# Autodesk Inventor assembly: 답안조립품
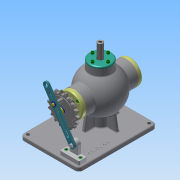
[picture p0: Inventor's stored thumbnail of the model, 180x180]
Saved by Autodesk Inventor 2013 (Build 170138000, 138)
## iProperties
Created: 2017-07
Part Number: 답안조립품
Document SubType Name: Assembly
Designer: Administrator
Author: Administrator
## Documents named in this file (20)
- C:\Users\Administrator\Desktop\370708V1006\답안조립품.iam
- C:\Users\Administrator\Desktop\370708V1006\본체.ipt
- C:\Users\Administrator\Desktop\370708V1006\본체커버.ipt
- C:\Users\Administrator\Desktop\370708V1006\베어링 6202.ipt
- C:\Users\Administrator\Desktop\370708V1006\뒤커버.ipt
- C:\Users\Administrator\Desktop\370708V1006\볼트 M4x12.ipt
- C:\Users\Administrator\Desktop\370708V1006\축.ipt
- C:\Users\Administrator\Desktop\370708V1006\앞커버.ipt
- C:\Users\Administrator\Desktop\370708V1006\오일실.ipt
- C:\Users\Administrator\Desktop\370708V1006\키 3 x 3 x 12.ipt
- C:\Users\Administrator\Desktop\370708V1006\슬라이드.ipt
- C:\Users\Administrator\Desktop\370708V1006\슬라이드 커버.ipt
- C:\Users\Administrator\Desktop\370708V1006\고정핀.ipt
- C:\Users\Administrator\Desktop\370708V1006\스프로킷.ipt
- C:\Users\Administrator\Desktop\370708V1006\연결대.ipt
- C:\Users\Administrator\Desktop\370708V1006\와셔 8x17.ipt
- C:\Users\Administrator\Desktop\370708V1006\너트 M8x1.ipt
- C:\Users\Administrator\Desktop\370708V1006\둥근머리 볼트 M4x8.ipt
- C:\Users\Administrator\Desktop\370708V1006\와셔 ISO 7093 A.ipt
- C:\Users\Administrator\Desktop\370708V1006\스프링.ipt
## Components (1 placed, 1 different names)
1. 고정핀:1 — 각도:5, 각도:6
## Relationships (2: Angle 2)
- 각도:5 [Angle]: 고정핀:1
- 각도:6 [Angle]: 고정핀:1
